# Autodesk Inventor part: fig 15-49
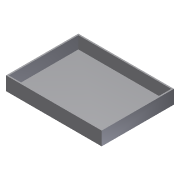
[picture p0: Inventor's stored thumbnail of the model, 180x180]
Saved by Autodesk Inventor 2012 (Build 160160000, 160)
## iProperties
Shininess: 77.0
Angle Display Precision: 2
Document Length Units: 11269
Document Angle Units: 11279
Document Time Units: 11290
Document Mass Units: 11283
Document Length Units Precision: 3
Document Angle Units Precision: 2
Compacted: True
Created: 2002-04
Part Number: fig 15-49
Document SubType Name: Sheet Metal
Density: 1 g/cm^3
Sheet Metal Rule: Default
Material: Default
Density: 0.0
Volumn: 0.0
Area: 0.0
PropertySet Name: Model Information
Control State: 0
Master: False
Checked Out: False
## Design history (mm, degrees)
sketch "Sketch1"
  geometry: L1 (-34, 28)-(36, 28); L2 (36, 28)-(36, -24.941); L3 (36, -24.941)-(-34, -24.941); L4 (-34, -24.941)-(-34, 28)
  constraints: 8 end point, 2 parallel, 1 horizontal, 1 perpendicular
extrude "Extrusion1" new body sketch "Sketch1" distance "d0" = 10; taper "d1" = 0 deg
shell "Shell1" dims "d2" = 1
body "Solid1"
other parameters: "Thickness" = 1, "BendRadius" = 1 (= Thickness), "BendReliefWidth" = 1 (= Thickness), "BendReliefDepth" = 0.5 (= 0.5 x Thickness), "CornerReliefSize" = 4 (= 4 x Thickness), "SeamGap" = 0.01, "MinimumRemnant" = 2 (= 2 x Thickness), "TransitionRadius" = 1 (= BendRadius), "JacobiRadiusSize" = 1 (= Thickness), "GapSize" = 1 (= Thickness)
